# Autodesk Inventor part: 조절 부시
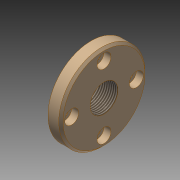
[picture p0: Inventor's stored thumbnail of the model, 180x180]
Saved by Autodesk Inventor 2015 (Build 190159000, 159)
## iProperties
Created: 2023-11
Part Number: 조절 부시
Material: 강철, 연강
Document SubType Name: Modeling
Designer: mdu-01
Density: 1 g/cm^3
Appearance: 기본값(1)
Author: mdu-01
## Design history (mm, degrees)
sketch "스케치1"
  geometry: L1 (-7, 0)-(6, 0); L2 (6, 0)-(6, 19); L3 (5, 20)-(0, 20); L4 (0, 20)-(0, 9); L5 (0, 9)-(-6, 9); L6 (-7, 8)-(-7, 0); L7 (6, 19)-(5, 20); L8 (-6, 9)-(-7, 8); 3 further points
  constraints: 18 end point, 6 point on line, 1 horizontal, 1 parallel, 1 vertical
  dimensions: "d0" = 6 distance between parallel lines of L2 L4; "d2" = 18 diameter of L5 L1; "d3" = 40 diameter of L3 L1; "d4" = 7 distance between parallel lines of L6 L4; "d5" = 1 distance of L2.end point (6, 20); "d6" = 1 distance of L3.start point (6, 20) (= d5); "d7" = 1 distance of L5.end point (-7, 9); "d8" = 1 distance of L6.start point (-7, 9) (= d7)
revolve "회전1" sketch "스케치1" stored, may be unused: angle "d9" = 90 deg
hole "구멍1" diameter "d12" = 12.917; stored, may be unused: countersink angle "d16" = 90 deg, drill point angle "d18" = 118 deg; dims "d10" = 10, "d11" = 10, "d13" = 6, "d14" = 4, "d15" = 2, "d17" = 8
sketch "스케치2"
  geometry: C1 r 1.23 at (0, 15) reference; 1 further point
hole "구멍2" sketch "스케치2" at (0, 15) diameter "d19" = 3.4; stored, may be unused: countersink angle "d23" = 90 deg, drill point angle "d25" = 118 deg; dims "d20" = 6, "d21" = 6.5, "d22" = 3.3, "d24" = 8
node "솔리드1"
pattern_circular "원형 패턴1" dims angle "d27" = 360 deg
node "참조1"
